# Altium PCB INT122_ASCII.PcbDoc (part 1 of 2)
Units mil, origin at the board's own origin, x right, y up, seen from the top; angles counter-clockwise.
Board outline 4500 x 3260 mil, 4 copper layers (Top Layer, GND Layer, VCC Layer, Bottom Layer), stack 61.6 mil thick; 94 components, 30 nets, 233 pads, 39 vias.
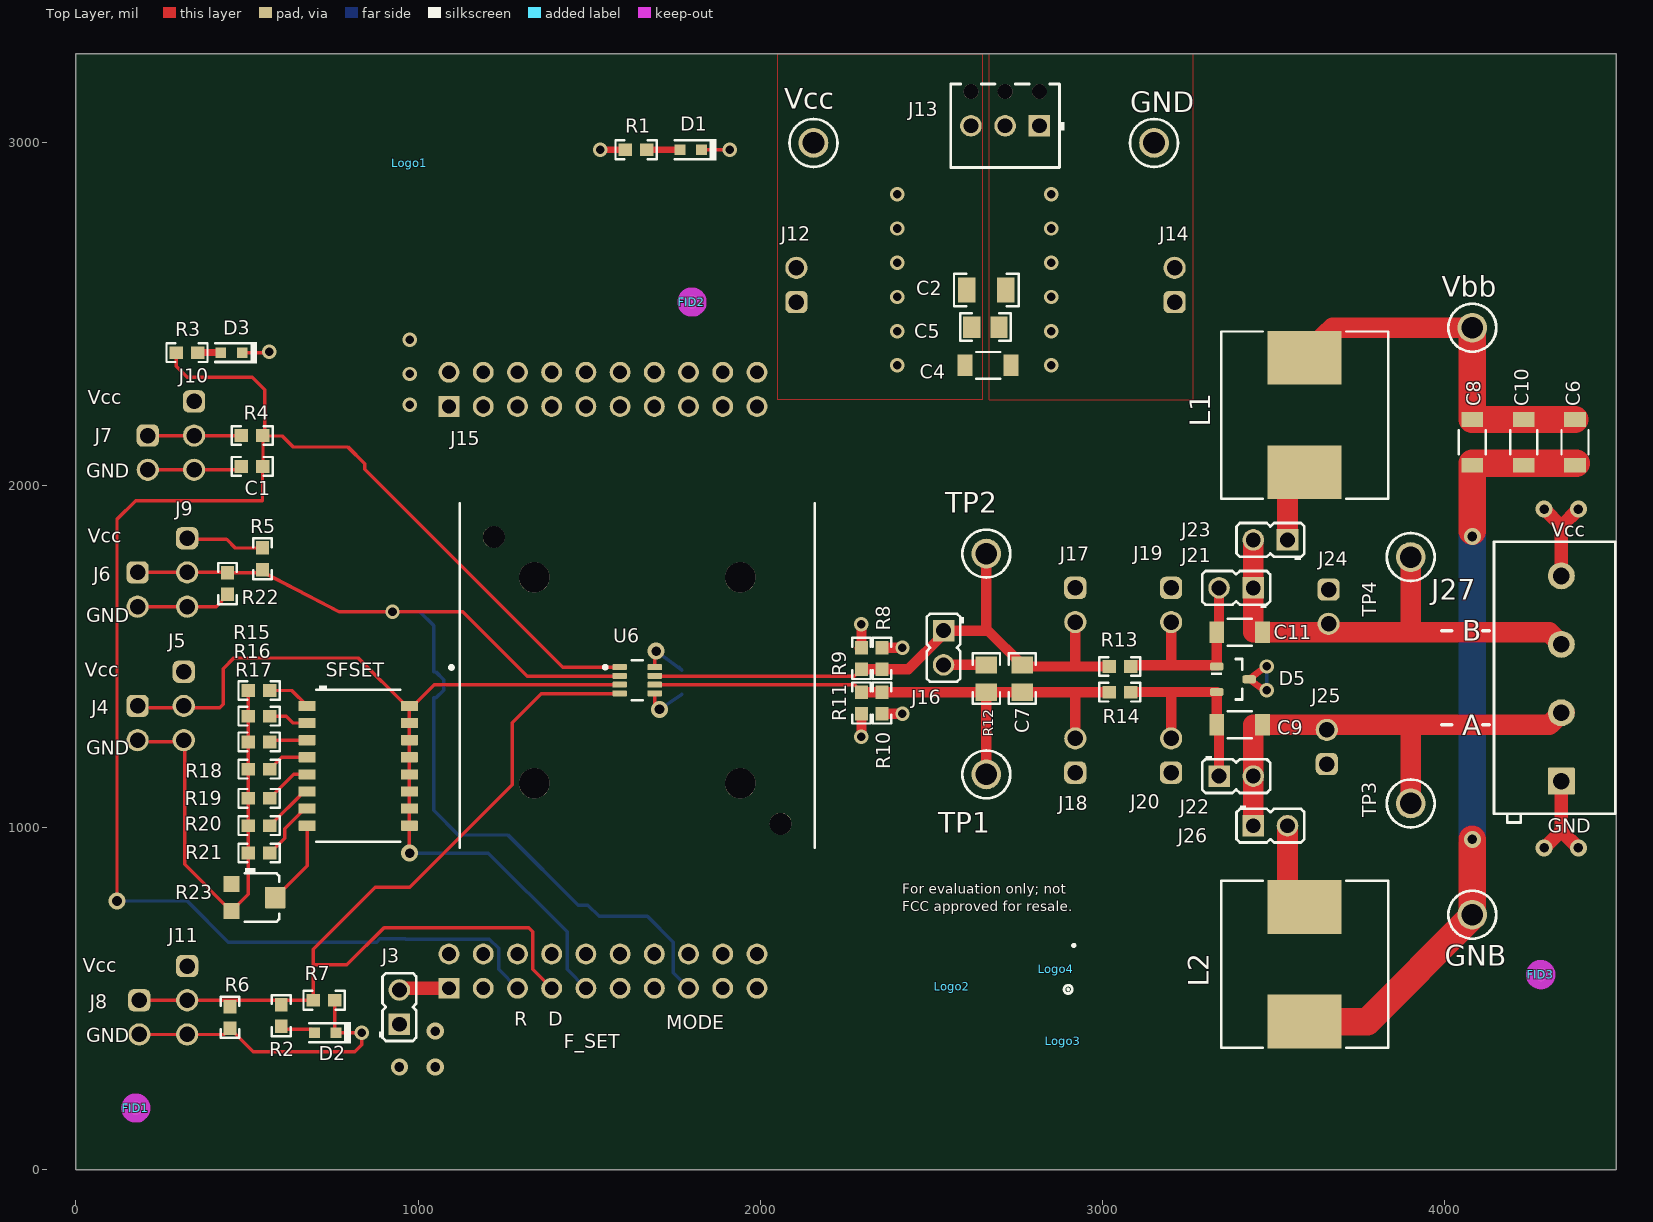
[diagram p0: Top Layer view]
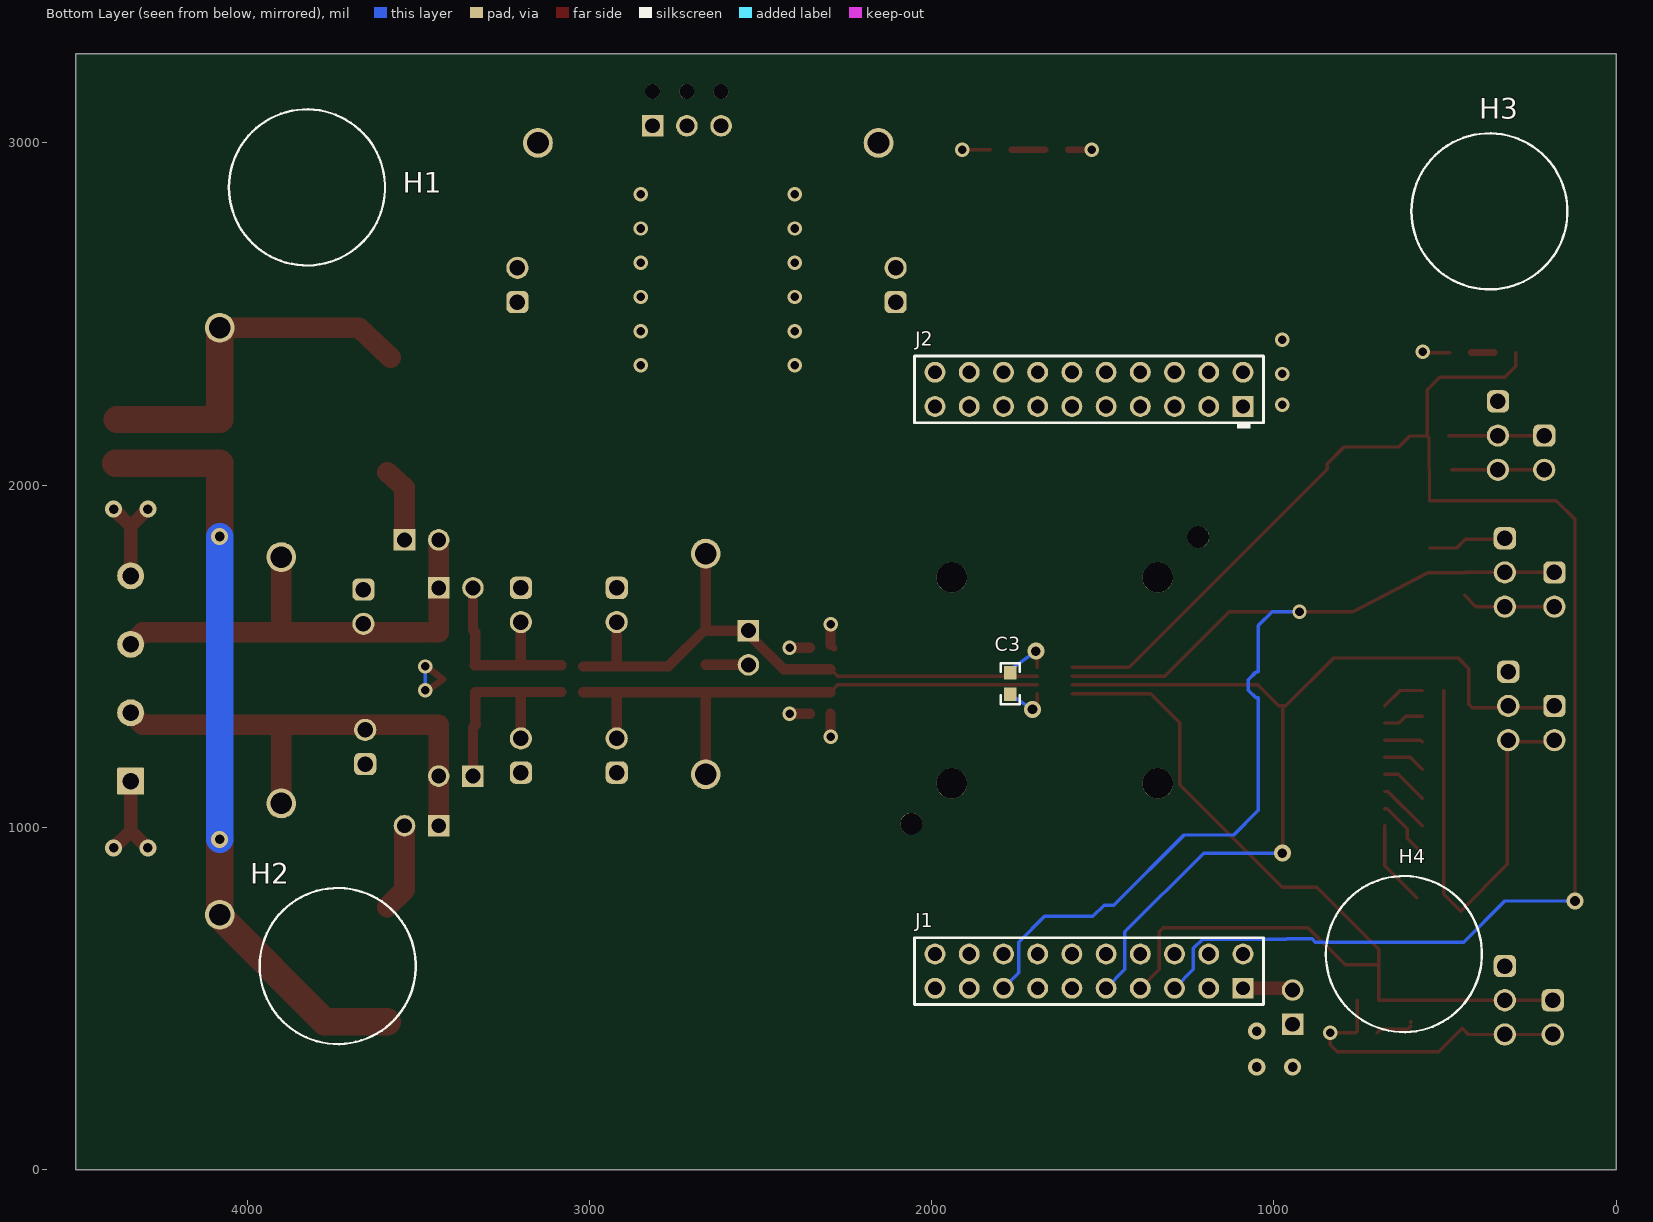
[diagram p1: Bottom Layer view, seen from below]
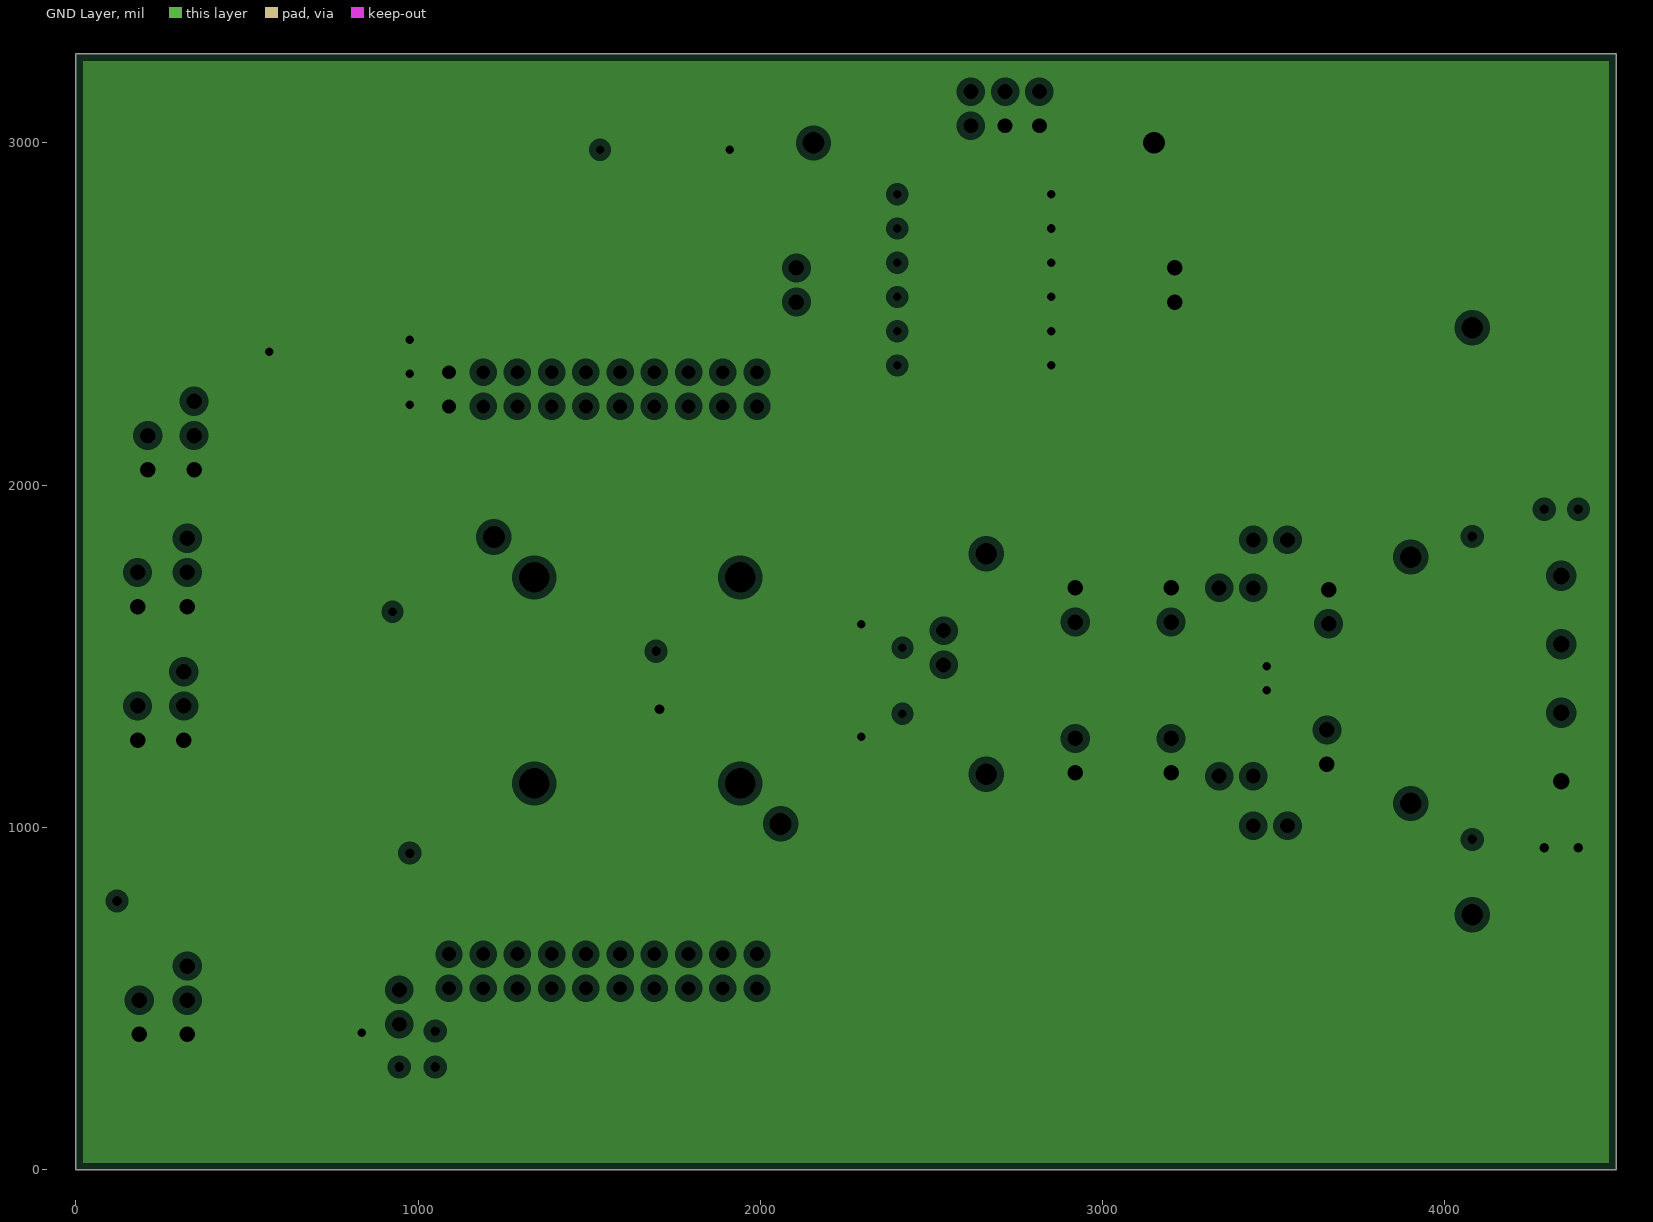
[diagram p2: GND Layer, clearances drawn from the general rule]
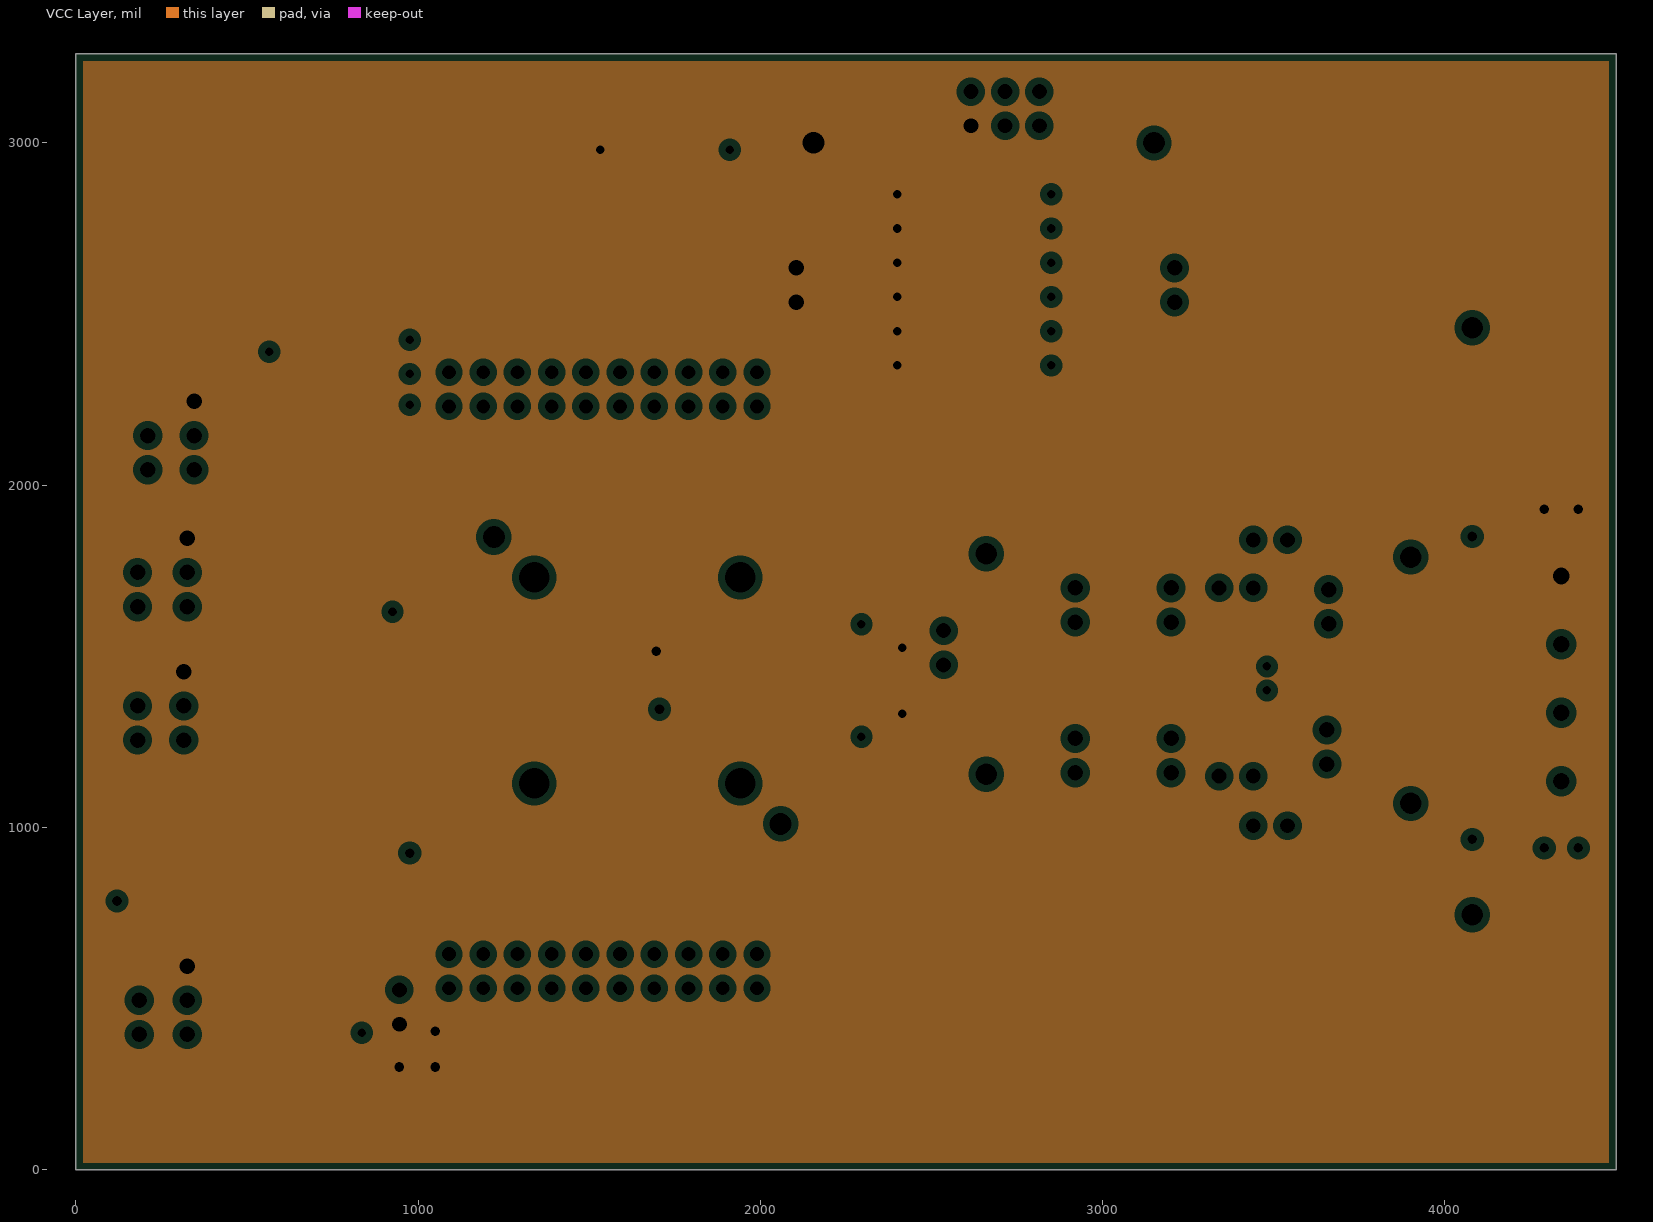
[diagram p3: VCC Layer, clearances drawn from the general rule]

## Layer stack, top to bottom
Top Solder: solder mask 0.4, Solder Resist, Dk 3.5
Top Layer: signal copper 1.4
Dielectric 1: prepreg 8, FR-4, Dk 4.2
GND Layer: plane copper 1.4, net GND_BRD
Dielectric 2: core 40, FR-4, Dk 4.2
VCC Layer: plane copper 1.4, net VCC_BRD
Dielectric 3: prepreg 8, FR-4, Dk 4.2
Bottom Layer: signal copper 1.4
Bottom Solder: solder mask 0.4, Solder Resist, Dk 3.5

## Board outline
0,0 4500,0 4500,3260 0,3260

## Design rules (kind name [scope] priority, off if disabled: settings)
AcuteAngle [All] p0: scope1count=1 scope1_0_kind=Board scope1_0_value=Board scope2count=1 scope2_0_kind=Board scope2_0_value=Board commentlength=0 minimum=4.50000000000000E+0001
AcuteAngle [All] p1: minimum=4.50000000000000E+0001 checktracksonly=FALSE
AssemblyTestPointUsage [All] p0: scope1count=1 scope1_0_kind=Board scope1_0_value=Board scope2count=1 scope2_0_kind=Board scope2_0_value=Board commentlength=0
AssemblyTestPointUsage [All] p1: valid=2
AssemblyTestpoint [All] p0: scope1count=1 scope1_0_kind=Board scope1_0_value=Board scope2count=1 scope2_0_kind=Board scope2_0_value=Board commentlength=0
BoardOutlineClearance [All] p0 off: scope1count=1 scope1_0_kind=Board scope1_0_value=Board scope2count=1 scope2_0_kind=Board scope2_0_value=Board commentlength=172 gap=75 // Protel DXP Scope 1 Expression Was: OnCopper and Not InComponentClass('Logo') and not InComponentClass('FiducialMark') and not InRegion(1000,500,4000,800) and not InPoly
BoardOutlineClearance BoardOutlineClearance_Poly [All] p0 off: scope1count=1 scope1_0_kind=Board scope1_0_value=Board scope2count=1 scope2_0_kind=Board scope2_0_value=Board commentlength=58 gap=25 // Protel DXP Scope 1 Expression Was: OnCopper and IsPoly
BoardOutlineClearance BoardOutlineClearance_MountingHoles [All] p0 off: scope1count=1 scope1_0_kind=Board scope1_0_value=Board scope2count=1 scope2_0_kind=Board scope2_0_value=Board commentlength=86 gap=40 // Protel DXP Scope 1 Expression Was: OnCopper and InComponentClass('Mounting Holes')
BoardOutlineClearance BoardOutlineClearance_MountingHoles [OnCopper and InComponentClass('Mounting Holes')] p1: gap=40 ignorepadtopadclearanceinfootprint=FALSE
BoardOutlineClearance BoardOutlineClearance_Poly [OnCopper and IsPoly] p2: gap=25 ignorepadtopadclearanceinfootprint=FALSE
BoardOutlineClearance [OnCopper and Not InComponentClass('Logo') and not InComponentClass('FiducialMark') and not InRegion(1000,500,4000,800) and not InPoly] p3: gap=75 ignorepadtopadclearanceinfootprint=FALSE
Clearance [All] p0: scope1count=1 scope1_0_kind=Board scope1_0_value=Board scope2count=1 scope2_0_kind=Board scope2_0_value=Board commentlength=0 gap=7.87
Clearance Clearance_FiducialMark [All] p0 off: scope1count=1 scope1_0_kind=Board scope1_0_value=Board scope2count=1 scope2_0_kind=Board scope2_0_value=Board commentlength=81 gap=0 // Protel DXP Scope 2 Expression Was: IsPad and InComponentClass('FiducialMark')
Clearance Clearance_Poly [All] p0 off: scope1count=1 scope1_0_kind=Board scope1_0_value=Board scope2count=1 scope2_0_kind=Board scope2_0_value=Board commentlength=48 gap=25 // Protel DXP Scope 1 Expression Was: InPolygon
Clearance Clearance_Keepouts [All] p0 off: scope1count=1 scope1_0_kind=Board scope1_0_value=Board scope2count=1 scope2_0_kind=Board scope2_0_value=Board commentlength=99 gap=0 // Protel DXP Scope 2 Expression Was: ((IsTrack Or IsArc) And Not InPoly) And IsFree and IsKeepOut
Clearance Clearance_Keepouts [((IsTrack Or IsArc) And Not InPoly) And IsFree and IsKeepOut vs ((IsTrack Or IsArc) And Not InPoly) And IsFree and IsKeepOut] p1: gap=0 ignorepadtopadclearanceinfootprint=FALSE
Clearance Clearance_Poly [InPolygon] p2: gap=25 ignorepadtopadclearanceinfootprint=FALSE except(0: Arc-Hole Track-Hole SMDPad-Hole THPad-Hole Via-Hole Fill-Hole Poly-Hole Region-Hole Text-Hole)
Clearance Clearance_FiducialMark [IsKeepOut and InComponentClass('FiducialMark') vs IsPad and InComponentClass('FiducialMark')] p3: gap=0 ignorepadtopadclearanceinfootprint=FALSE
Clearance [All] p4: gap=7.87 ignorepadtopadclearanceinfootprint=FALSE except(0: Arc-Hole Track-Hole SMDPad-Hole THPad-Hole Via-Hole Fill-Hole Poly-Hole Region-Hole Text-Hole)
ComponentClearance ComponentClearance_THtoSMT_Socket [All] p0: scope1count=1 scope1_0_kind=Component scope1_0_value=JS scope2count=1 scope2_0_kind=Component scope2_0_value=U6 commentlength=0 gap=0 collisioncheckmode=3
ComponentClearance [All] p0: scope1count=1 scope1_0_kind=Board scope1_0_value=Board scope2count=1 scope2_0_kind=Board scope2_0_value=Board commentlength=0 gap=30 collisioncheckmode=3
ComponentClearance ComponentClearance_THtoTH [All] p0 off: scope1count=1 scope1_0_kind=Board scope1_0_value=Board scope2count=1 scope2_0_kind=Board scope2_0_value=Board commentlength=54 gap=30 collisioncheckmode=3 // Protel DXP Scope 2 Expression Was: IsThruComponent
ComponentClearance ComponentClearance_THtoSMT [All] p0 off: scope1count=1 scope1_0_kind=Board scope1_0_value=Board scope2count=1 scope2_0_kind=Board scope2_0_value=Board commentlength=53 gap=40 collisioncheckmode=3 // Protel DXP Scope 2 Expression Was: IsSMTComponent
ComponentClearance ComponentClearance_SmallPassives [All] p0 off: scope1count=1 scope1_0_kind=Board scope1_0_value=Board scope2count=1 scope2_0_kind=Board scope2_0_value=Board commentlength=508 gap=14.96 collisioncheckmode=3 // Protel DXP Scope 2 Expression Was: HasFootprint('0201*') or HasFootprint('0402*') or HasFootprint('0508') or HasFootprint('0603*') or HasFootprint('0612') or HasFootprint('0805*') or HasFootprint('0815*') or HasFootprint('0830*') or HasFootprint('1206*') or HasFootprint('1210*') or HasFootprint('1808*') or HasFootprint('1812*') or HasFootprint('1825*') or HasFootprint('2010*') or HasFootprint('2220*') or HasFootprint('2225*') or HasFootprint('2512*') or HasFootprint('2728*') or HasFootprint('3518*')
ComponentClearance ComponentClearance_MountingHoles [All] p0: scope1count=1 scope1_0_kind=ComponentClass scope1_0_value="Mounting Holes" scope2count=1 scope2_0_kind=Board scope2_0_value=Board commentlength=0 gap=250 collisioncheckmode=3
ComponentClearance ComponentClearance_ScrewToNut [All] p0 off: scope1count=1 scope1_0_kind=Board scope1_0_value=Board scope2count=1 scope2_0_kind=Board scope2_0_value=Board commentlength=71 gap=5 collisioncheckmode=3 // Protel DXP Scope 2 Expression Was: (HasFootprint('Keystone_1902C'))
ComponentClearance ComponentClearance_Logo [All] p0: scope1count=1 scope1_0_kind=ComponentClass scope1_0_value=Logo scope2count=1 scope2_0_kind=Board scope2_0_value=Board commentlength=0 gap=30 collisioncheckmode=3
ComponentClearance ComponentClearance_Shunt [All] p0: scope1count=1 scope1_0_kind=ComponentClass scope1_0_value=Header scope2count=1 scope2_0_kind=ComponentClass scope2_0_value=Shunt commentlength=0 gap=0 collisioncheckmode=3
ComponentClearance ComponentClearance_MountingHoles_FiducialMarks [All] p0: scope1count=1 scope1_0_kind=ComponentClass scope1_0_value="Mounting Holes" scope2count=1 scope2_0_kind=ComponentClass scope2_0_value=FiducialMark commentlength=0 gap=50 collisioncheckmode=3
ComponentClearance ComponentClearance_L1_Multipad [All] p0: scope1count=1 scope1_0_kind=Component scope1_0_value=L1 scope2count=1 scope2_0_kind=Component scope2_0_value=L1B commentlength=0 gap=-1 collisioncheckmode=3
ComponentClearance ComponentClearance_L2_Multipad [All] p0: scope1count=1 scope1_0_kind=Component scope1_0_value=L2 scope2count=1 scope2_0_kind=Component scope2_0_value=L2B commentlength=0 gap=-1 collisioncheckmode=3
ComponentClearance ComponentClearance_C13_Multipad [All] p0: scope1count=1 scope1_0_kind=Component scope1_0_value=C13 scope2count=1 scope2_0_kind=Component scope2_0_value=C13B commentlength=0 gap=-1 collisioncheckmode=3
ComponentClearance ComponentClearance_C14_Multipad [All] p0: scope1count=1 scope1_0_kind=Component scope1_0_value=C14 scope2count=1 scope2_0_kind=Component scope2_0_value=C14B commentlength=0 gap=-1 collisioncheckmode=3
ComponentClearance ComponentClearance_THtoSMT_Socket [InComponent('JS') vs InComponent('U6')] p1: gap=0 collisioncheckmode=3 verticalgap=0 showdistances=FALSE
ComponentClearance ComponentClearance_L1_Multipad [InComponent('L1') vs InComponent('L1B')] p2: gap=-1 collisioncheckmode=3 verticalgap=100000 showdistances=FALSE
ComponentClearance ComponentClearance_L2_Multipad [InComponent('L2') vs InComponent('L2B')] p3: gap=-1 collisioncheckmode=3 verticalgap=100000 showdistances=FALSE
ComponentClearance ComponentClearance_C13_Multipad [InComponent('C13') vs InComponent('C13B')] p4: gap=-1 collisioncheckmode=3 verticalgap=100000 showdistances=FALSE
ComponentClearance ComponentClearance_C14_Multipad [InComponent('C14') vs InComponent('C14B')] p5: gap=-1 collisioncheckmode=3 verticalgap=100000 showdistances=FALSE
ComponentClearance ComponentClearance_MountingHoles_FiducialMarks [InComponentClass('Mounting Holes') vs InComponentClass('FiducialMark')] p6: gap=50 collisioncheckmode=3 verticalgap=10 showdistances=FALSE
ComponentClearance ComponentClearance_Shunt [InComponentClass('Header') vs InComponentClass('Shunt')] p7: gap=0 collisioncheckmode=3 verticalgap=0 showdistances=FALSE
ComponentClearance ComponentClearance_Logo [InComponentClass('Logo')] p8: gap=30 collisioncheckmode=3 verticalgap=10 showdistances=FALSE
ComponentClearance ComponentClearance_ScrewToNut [(HasFootprint('NY PMS 440 0025 PH')) vs (HasFootprint('Keystone_1902C'))] p9: gap=5 collisioncheckmode=3 verticalgap=10 showdistances=FALSE
ComponentClearance ComponentClearance_MountingHoles [InComponentClass('Mounting Holes')] p10: gap=250 collisioncheckmode=3 verticalgap=100000 showdistances=FALSE
ComponentClearance ComponentClearance_SmallPassives [HasFootprint('0201*') or HasFootprint('0402*') or HasFootprint('0508') or HasFootprint('0603*') or HasFootprint('0612') or HasFootprint('0805*') or HasFootprint('0815*') or HasFootprint('0830*') or HasFootprint('1206*') or HasFootprint('1210*') or HasFootprint('1808*') or HasFootprint('1812*') or HasFootprint('1825*') or HasFootprint('2010*') or HasFootprint('2220*') or HasFootprint('2225*') or HasFootprint('2512*') or HasFootprint('2728*') or HasFootprint('3518*') vs HasFootprint('0201*') or HasFootprint('0402*') or HasFootprint('0508') or HasFootprint('0603*') or HasFootprint('0612') or HasFootprint('0805*') or HasFootprint('0815*') or HasFootprint('0830*') or HasFootprint('1206*') or HasFootprint('1210*') or HasFootprint('1808*') or HasFootprint('1812*') or HasFootprint('1825*') or HasFootprint('2010*') or HasFootprint('2220*') or HasFootprint('2225*') or HasFootprint('2512*') or HasFootprint('2728*') or HasFootprint('3518*')] p11: gap=14.96 collisioncheckmode=3 verticalgap=10 showdistances=FALSE
ComponentClearance ComponentClearance_THtoSMT [IsThruComponent vs IsSMTComponent] p12: gap=40 collisioncheckmode=3 verticalgap=30 showdistances=FALSE
ComponentClearance ComponentClearance_THtoTH [IsThruComponent vs IsThruComponent] p13: gap=30 collisioncheckmode=3 verticalgap=30 showdistances=FALSE
ComponentClearance [All] p14: gap=30 collisioncheckmode=3 verticalgap=10 showdistances=FALSE
DiffPairsRouting [All] p0: scope1count=1 scope1_0_kind=Board scope1_0_value=Board scope2count=1 scope2_0_kind=Board scope2_0_value=Board commentlength=0
DiffPairsRouting [All] p1: maxlimit=100 minlimit=10 mostfreqgap=10 toplayer_minwidth=15 toplayer_maxwidth=15 toplayer_prefwidth=15 bottomlayer_minwidth=15 bottomlayer_maxwidth=15 bottomlayer_prefwidth=15 maxuncoupledlength=1000
FabricationTestPointUsage TestPointUsage [All] p0: scope1count=1 scope1_0_kind=Board scope1_0_value=Board scope2count=1 scope2_0_kind=Board scope2_0_value=Board commentlength=0 valid=2 allowmultiple=FALSE
FabricationTestPointUsage TestPointUsage [All] p1: valid=2 allowmultiple=FALSE
FabricationTestpoint Testpoint [All] p0: scope1count=1 scope1_0_kind=Board scope1_0_value=Board scope2count=1 scope2_0_kind=Board scope2_0_value=Board commentlength=0 side=3 testpointundercomponent=TRUE minsize=40 maxsize=100 preferedsize=60 minholesize=0 maxholesize=40 preferedholesize=32 testpointgrid=1
FabricationTestpoint Testpoint [All] p1: side=3 testpointundercomponent=TRUE minsize=40 maxsize=100 preferedsize=60 minholesize=0 maxholesize=40 preferedholesize=32 testpointgrid=1 allowsidetop=TRUE allowsidebottom=TRUE usegrid=TRUE gridtolerance=0.01
FanoutControl Fanout_Small [All] p0 off: scope1count=1 scope1_0_kind=Board scope1_0_value=Board scope2count=1 scope2_0_kind=Board scope2_0_value=Board commentlength=84 // Protel DXP Scope 1 Expression Was: (CompPinCount < 5)   Fanout_Small (Default Rule)
FanoutControl Fanout_Default [All] p0: scope1count=1 scope1_0_kind=Board scope1_0_value=Board scope2count=1 scope2_0_kind=Board scope2_0_value=Board commentlength=30 // Fanout_Default (Default Rule)
FanoutControl Fanout_SOIC [All] p0 off: scope1count=1 scope1_0_kind=Board scope1_0_value=Board scope2count=1 scope2_0_kind=Board scope2_0_value=Board commentlength=71 // Protel DXP Scope 1 Expression Was: IsSOIC   Fanout_SOIC (Default Rule)
FanoutControl Fanout_BGA [All] p0 off: scope1count=1 scope1_0_kind=Board scope1_0_value=Board scope2count=1 scope2_0_kind=Board scope2_0_value=Board commentlength=69 // Protel DXP Scope 1 Expression Was: IsBGA   Fanout_BGA (Default Rule)
FanoutControl Fanout_LCC [All] p0 off: scope1count=1 scope1_0_kind=Board scope1_0_value=Board scope2count=1 scope2_0_kind=Board scope2_0_value=Board commentlength=69 // Protel DXP Scope 1 Expression Was: IsLCC   Fanout_LCC (Default Rule)
FanoutControl Fanout_LCC [IsLCC] p1: bgadir=Out bgaviamode=Centered fanoutstyle=Auto fanoutdirection=Alternating viagrid=1 // Fanout_LCC (Default Rule)
FanoutControl Fanout_BGA [IsBGA] p2: bgadir=Out bgaviamode=Centered fanoutstyle=Auto fanoutdirection=Alternating viagrid=1 // Fanout_BGA (Default Rule)
FanoutControl Fanout_Default [All] p4: bgadir=Out bgaviamode=Centered fanoutstyle=Auto fanoutdirection=Alternating viagrid=1 // Fanout_Default (Default Rule)
FanoutControl Fanout_Small [(CompPinCount < 5)] p5: bgadir=Out bgaviamode=Centered fanoutstyle=Auto fanoutdirection=OutThenIn viagrid=1 // Fanout_Small (Default Rule)
Height [All] p0: scope1count=1 scope1_0_kind=Board scope1_0_value=Board scope2count=1 scope2_0_kind=Board scope2_0_value=Board commentlength=0
HoleSize [All] p0: scope1count=1 scope1_0_kind=Board scope1_0_value=Board scope2count=1 scope2_0_kind=Board scope2_0_value=Board commentlength=0 absolutevalues=TRUE maxlimit=251 minlimit=7.87 maxpercent=80.000 minpercent=20.000
HoleSize [All] p1: absolutevalues=TRUE maxlimit=251 minlimit=7.87 maxpercent=80.000 minpercent=20.000
HoleToHoleClearance [All] p0: scope1count=1 scope1_0_kind=Board scope1_0_value=Board scope2count=1 scope2_0_kind=Board scope2_0_value=Board commentlength=0
LayerPairs [All] p0: scope1count=1 scope1_0_kind=Board scope1_0_value=Board scope2count=1 scope2_0_kind=Board scope2_0_value=Board commentlength=0 enforce=TRUE
MinimumAnnularRing [All] p0: scope1count=1 scope1_0_kind=Board scope1_0_value=Board scope2count=1 scope2_0_kind=Board scope2_0_value=Board commentlength=0 minimumring=8
MinimumAnnularRing MinimumAnnularRing_ThermalPadVias [All] p0 off: scope1count=1 scope1_0_kind=Board scope1_0_value=Board scope2count=1 scope2_0_kind=Board scope2_0_value=Board commentlength=63 minimumring=5.91 // Protel DXP Scope 1 Expression Was: IsVia and InAnyComponent
MinimumAnnularRing MinimumAnnularRing_ThermalPadVias [IsVia and InAnyComponent] p1: minimumring=5.91
MinimumAnnularRing [All] p2: minimumring=8
MinimumSolderMaskSliver [All] p0: scope1count=1 scope1_0_kind=Board scope1_0_value=Board scope2count=1 scope2_0_kind=Board scope2_0_value=Board commentlength=0
MinimumSolderMaskSliver MinimumSolderMaskSliver_Logo [All] p0: scope1count=1 scope1_0_kind=ComponentClass scope1_0_value=Logo scope2count=1 scope2_0_kind=ComponentClass scope2_0_value=Logo commentlength=0
MinimumSolderMaskSliver MinimumSolderMaskSliver_Logo [InComponentClass('Logo') vs InComponentClass('Logo')] p1: minsoldermaskwidth=0.7
MinimumSolderMaskSliver [All] p2: minsoldermaskwidth=3.94
NetAntennae [All] p0: scope1count=1 scope1_0_kind=Board scope1_0_value=Board scope2count=1 scope2_0_kind=Board scope2_0_value=Board commentlength=0
PasteMaskExpansion [All] p0: scope1count=1 scope1_0_kind=Board scope1_0_value=Board scope2count=1 scope2_0_kind=Board scope2_0_value=Board commentlength=0 expansion=0
PlaneClearance [All] p0: scope1count=1 scope1_0_kind=Board scope1_0_value=Board scope2count=1 scope2_0_kind=Board scope2_0_value=Board commentlength=0 clearance=20
PlaneClearance [All] p1: clearance=20
PlaneConnect [All] p0: scope1count=1 scope1_0_kind=Board scope1_0_value=Board scope2count=1 scope2_0_kind=Board scope2_0_value=Board commentlength=0 planeconnectstyle=Relief reliefexpansion=10 reliefentries=4 reliefconductorwidth=10 reliefairgap=10
PlaneConnect [All] p1: planeconnectstyle=Relief reliefexpansion=10 reliefentries=4 reliefconductorwidth=10 reliefairgap=10
PolygonConnect [All] p0: scope1count=1 scope1_0_kind=Board scope1_0_value=Board scope2count=1 scope2_0_kind=Board scope2_0_value=Board commentlength=0 connectstyle=Relief reliefconductorwidth=15 reliefentries=4 polygonreliefangle="90 Angle"
PolygonConnect [All] p1: connectstyle=Relief reliefconductorwidth=15 reliefentries=4 polygonreliefangle="90 Angle" airgapwidth=7
RoutingCorners [All] p0: scope1count=1 scope1_0_kind=Board scope1_0_value=Board scope2count=1 scope2_0_kind=Board scope2_0_value=Board commentlength=0 cornerstyle=45-Degree minsetback=100 maxsetback=100
RoutingLayers [All] p0: scope1count=1 scope1_0_kind=Board scope1_0_value=Board scope2count=1 scope2_0_kind=Board scope2_0_value=Board commentlength=0 top layer=Automatic bottom layer=Automatic
RoutingPriority [All] p0: scope1count=1 scope1_0_kind=Board scope1_0_value=Board scope2count=1 scope2_0_kind=Board scope2_0_value=Board commentlength=0
RoutingTopology [All] p0: scope1count=1 scope1_0_kind=Board scope1_0_value=Board scope2count=1 scope2_0_kind=Board scope2_0_value=Board commentlength=0 topology=Shortest
RoutingVias [All] p0: scope1count=1 scope1_0_kind=Board scope1_0_value=Board scope2count=1 scope2_0_kind=Board scope2_0_value=Board commentlength=0 holewidth=25 width=42 viastyle="Through Hole" minholewidth=7.87 minwidth=26 maxholewidth=40 maxwidth=65
RoutingVias ThermalPadVias [All] p0 off: scope1count=1 scope1_0_kind=Board scope1_0_value=Board scope2count=1 scope2_0_kind=Board scope2_0_value=Board commentlength=63 holewidth=7.87 width=19.68 viastyle="Through Hole" minholewidth=7.87 minwidth=19.68 maxholewidth=12.99 maxwidth=23.62 // Protel DXP Scope 1 Expression Was: IsVia and InAnyComponent
RoutingVias ThermalPadVias [IsVia and InAnyComponent] p1: holewidth=7.87 width=19.68 viastyle="Through Hole" minholewidth=7.87 minwidth=19.68 maxholewidth=12.99 maxwidth=23.62
RoutingVias [All] p2: holewidth=25 width=42 viastyle="Through Hole" minholewidth=7.87 minwidth=26 maxholewidth=40 maxwidth=65
ShortCircuit [All] p0: scope1count=1 scope1_0_kind=Board scope1_0_value=Board scope2count=1 scope2_0_kind=Board scope2_0_value=Board commentlength=0 allowed=FALSE
SilkToBoardRegionClearance [All] p0 off: scope1count=1 scope1_0_kind=Board scope1_0_value=Board scope2count=1 scope2_0_kind=Board scope2_0_value=Board commentlength=130 // Protel DXP Scope 1 Expression Was: Not ((IsComment or IsDesignator) And (Hide <> 'False')) and not InRegion(1000,500,4000,800)
SilkToBoardRegionClearance [Not ((IsComment or IsDesignator) And (Hide <> 'False')) and not InRegion(1000,500,4000,800)] p1:
SilkToSilkClearance [All] p0: scope1count=1 scope1_0_kind=Board scope1_0_value=Board scope2count=1 scope2_0_kind=Board scope2_0_value=Board commentlength=0
SilkToSilkClearance SilkToSilkClearance_Pb-FreeLogo [All] p0 off: scope1count=1 scope1_0_kind=Board scope1_0_value=Board scope2count=1 scope2_0_kind=Board scope2_0_value=Board commentlength=120 // Protel DXP Scope 2 Expression Was: (HasFootprint('Pb-Free_Overlay_Medium') OR HasFootprint('Pb-Free_Overlay_Small'))
SilkToSilkClearance SilkToSilkClearance_Pb-FreeLogo [(HasFootprint('Pb-Free_Overlay_Medium') OR HasFootprint('Pb-Free_Overlay_Small')) vs (HasFootprint('Pb-Free_Overlay_Medium') OR HasFootprint('Pb-Free_Overlay_Small'))] p1: silktosilkclearance=0
SilkToSilkClearance [All] p2: silktosilkclearance=4
SilkToSolderMaskClearance "Silk to Solder Mask Opening" [All] p0: scope1count=1 scope1_0_kind=Board scope1_0_value=Board scope2count=1 scope2_0_kind=Board scope2_0_value=Board commentlength=0
SilkToSolderMaskClearance SilkToComponentPadClearance [All] p0 off: scope1count=1 scope1_0_kind=Board scope1_0_value=Board scope2count=1 scope2_0_kind=Board scope2_0_value=Board commentlength=87 // Protel DXP Scope 1 Expression Was: (IsPad or IsFill or IsRegion) and InAnycomponent
SilkToSolderMaskClearance SilkToComponentPadClearance [(IsPad or IsFill or IsRegion) and InAnycomponent] p1: minsilkscreentomaskgap=5 clearancetoexposedcopper=TRUE
SilkToSolderMaskClearance "Silk to Solder Mask Opening" [All] p2: minsilkscreentomaskgap=4 clearancetoexposedcopper=FALSE
SolderMaskExpansion [All] p0: scope1count=1 scope1_0_kind=Board scope1_0_value=Board scope2count=1 scope2_0_kind=Board scope2_0_value=Board commentlength=0 expansion=1.97
SolderMaskExpansion [All] p1: expansion=1.97
UnRoutedNet [All] p0: scope1count=1 scope1_0_kind=Board scope1_0_value=Board scope2count=1 scope2_0_kind=Board scope2_0_value=Board commentlength=0
UnpouredPolygon [All] p0: scope1count=1 scope1_0_kind=Board scope1_0_value=Board scope2count=1 scope2_0_kind=Board scope2_0_value=Board commentlength=0
Width [All] p0: scope1count=1 scope1_0_kind=Board scope1_0_value=Board scope2count=1 scope2_0_kind=Board scope2_0_value=Board commentlength=0 maxlimit=100 minlimit=6 preferedwidth=10
Width [All] p1: maxlimit=100 minlimit=6 preferedwidth=10 checkconnectedcopper=TRUE
14 further rules are at their usual default settings.

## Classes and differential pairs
component class Header: J3 J4 J5 J6 J7 J8 J9 J10 J11 J12 J14 J16 J17 J18 J19 J20 J21 J22 J23 J24 J25 J26 JD1 JF1 JM1 JR1 TL_A tn
component class AssemblyNote: ZZ1 ZZ2 ZZ3 ZZ4
component class FiducialMark: FID1 FID2 FID3
component class EVM_Hardware: FID1 FID2 FID3 H1 H2 H3 H4 Logo1 Logo2 Logo3 Logo4 SH-J1 SH-J2 ZZ1 ZZ2 ZZ3 ZZ4
component class Logo: Logo1

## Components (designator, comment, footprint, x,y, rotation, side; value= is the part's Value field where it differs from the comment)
C1 "06035A150JAT2A" 0603 515,2055 r180 top
C2 "12063C105KAT2A" 1206 2660,2570 r0 top
C3 "C0603C104K9PAC7867" 0603 1770,1420 r90 bottom
C4 "C3216X7R1V106K160AC" 1206_180 2665,2350 r0 top
C5 "GRM21BR61A476ME15L" 0805_HV 2657.5,2461.85 r180 top
C6 "C3216X5R1E476M160AC" 1206_190 4380,2125 r90 top
C7 "08053C104KAT2A" 0805_HV 2765,1435 r270 top
C8 "CGA5L2X7R2A105K160AA" 1206_180 4080,2125 r90 top
C9 "CGA5L2X7R2A105K160AA" 1206_180 3400.25,1300.3 r180 top
C10 "CL31B106KBHNNNE" 1206_180 4230,2125 r90 top
C11 "CGA5L2X7R2A105K160AA" 1206_180 3400.25,1570.3 r180 top
D1 "150060BS75000" WL-SMCW_Blue 1796.5,2980 r180 top
D2 "150060GS75000" WL-SMCW_GREEN 728.7,400 r180 top
D3 "150060RS75000" WL-SMCW_RED 454.45,2387.2 r180 top
D5 "CDSOT23-T12C" SOT-23 3380.56,1432.86 r0 top
FID1 "Fiducial" Fiducial10-20 175,180 r0 top
FID2 "Fiducial" Fiducial10-20 1800,2535 r0 top
FID3 "Fiducial" Fiducial10-20 4280,570 r90 top
GNB "5011" Keystone5011 4080,745 r0 top
GND "5011" Keystone5011 3150,3000 r180 top
H1 "SJ-5303 (CLEAR)" Bumpon_SJ5003Transparent 3825,2870 r90 bottom
H2 "SJ-5303 (CLEAR)" Bumpon_SJ5003Transparent 3735,595 r90 bottom
H3 "SJ-5303 (CLEAR)" Bumpon_SJ5003Transparent 370,2800 r90 bottom
H4 "SJ-5303 (CLEAR)" Bumpon_SJ5003Transparent 620,630 r180 bottom
J1 "SSQ-110-23-F-D" Samtec_SSQ-110-23-F-D 1540,580 r0 bottom
J2 "SSQ-110-23-F-D" Samtec_SSQ-110-23-F-D 1540,2280 r0 bottom
J3 "961102-6404-AR" 3M_961102-6404-AR 945,475 r90 top
J4 "61300211121" WURTH_61300211121 180,1305 r270 top
J5 "61300311121" WURTH_61300311121 315,1355 r270 top
J6 "61300211121" WURTH_61300211121 180,1695 r270 top
J7 "61300211121" WURTH_61300211121 210,2095 r270 top
J8 "61300211121" WURTH_61300211121 185,445 r270 top
J9 "61300311121" WURTH_61300311121 325,1745 r270 top
J10 "61300311121" WURTH_61300311121 345,2145 r270 top
J11 "61300311121" WURTH_61300311121 325,495 r270 top
J12 "61300211121" WURTH_61300211121 2105,2585 r90 top
J13 "1725669" Phoenix_1725669 2715,3050 r180 top
J14 "61300211121" WURTH_61300211121 3210,2585 r90 top
J15 "SK02-0008SOP-GS-04A" FP-SK02-0008SOP-GS-04A_SOCKET-MFG 1640,1415 r0 top
J16 "961102-6404-AR" 3M_961102-6404-AR 2535,1525 r270 top
J17 "61300211121" WURTH_61300211121 2920,1650 r270 top
J18 "61300211121" WURTH_61300211121 2920,1210 r90 top
J19 "61300211121" WURTH_61300211121 3200,1650 r270 top
J20 "61300211121" WURTH_61300211121 3200,1210 r90 top
J21 "961102-6404-AR" 3M_961102-6404-AR 3390,1700 r180 top
J22 "961102-6404-AR" 3M_961102-6404-AR 3390,1150 r0 top
J23 "961102-6404-AR" 3M_961102-6404-AR 3490,1840 r180 top
J24 "61300211121" WURTH_61300211121 3660,1645 r270 top
J25 "61300211121" WURTH_61300211121 3655,1235 r90 top
J26 "961102-6404-AR" 3M_961102-6404-AR 3490,1005 r0 top
J27 "ED120/4DS" On-Shore_ED120_4DS 4340,1435 r90 top
L1 "MSS1278T-124KLB" MSS1278T 3590,2205 r270 top
L2 "MSS1278T-124KLB" MSS1278T 3590,600 r270 top
Logo1 "Texas Instruments" TI_Stacked_Overlay_Small 975,2940 r0 top
Logo2 "CE Mark" CE_Mark_5mm 2560,535 r0 top
Logo3 "FCC disclaimer" FCC_disclaimer 2885,375 r270 top
Logo4 "WEEE logo" WEEE_Minimum 2865,585 r0 top
R1 "CRCW06031K00JNEA" 0603 1636.5,2980 r0 top
R2 "CRCW06031K00JNEA" 0603 599.8,450 r270 top
R3 "CRCW06031K00JNEA" 0603 324.45,2387.2 r0 top
R4 "RCS06030000Z0EA" 0603 515,2145 r0 top
R5 "RC1608J103CS" 0603 545,1785 r90 top
R6 "RCP0603W50R0GEB" 0603 450,445 r90 top
R7 "RC1608J103CS" 0603 725,495 r180 top
R8 "RC0603JR-0715KL" 0603 2355,1493.7 r90 top
R9 "RC0603FR-0712K4L" 0603 2295,1493.7 r270 top
R10 "RC0603FR-0712K4L" 0603 2355,1363.5 r270 top
R11 "RC0603JR-0715KL" 0603 2295,1363.5 r90 top
R12 "ERJ-P06J121V" 0805_HV 2660,1435 r90 top
R13 "RCS06030000Z0EA" 0603 3050,1470.26 r0 top
R14 "RCS06030000Z0EA" 0603 3050,1395 r0 top
R15 "ERJ-3EKF1501V" 0603 535,1400 r0 top
R16 "CRCW06034K42FKEA" 0603 535,1325 r0 top
R17 "CRCW06039K31FKEA" 0603 535,1250 r0 top
R18 "RC0603FR-0712K4L" 0603 535,1170 r0 top
R19 "RC0603FR-0719K1L" 0603 535,1085 r0 top
R20 "RC0603FR-0749K9L" 0603 535,1005 r0 top
R21 "CRCW060376K8FKEA" 0603 535,925 r0 top
R22 "RCP0603W50R0GEB" 0603 442.5,1712.5 r90 top
R23 "TC33X-2-103E" Bourns_TC33X-2 525,795 r0 top
SFSET "1-1571983-1" SW_1-1571983-1 825,1180 r0 top
SH-J1 "M7582-05" Harwin_M7582-05 4898,161 r90 top
SH-J2 "M7582-05" Harwin_M7582-05 4648,161 r90 top
TP1 "5012" Keystone5012 2660,1155 r0 top
TP2 "5012" Keystone5012 2660,1800 r0 top
TP3 "5012" Keystone5012 3900,1070 r0 top
TP4 "5012" Keystone5012 3900,1790 r0 top
U6 "THVD8000DDF" DDF0008A-MFG 1640,1430 r0 top
Vbb "5010" Keystone5010 4080,2460 r0 top
Vcc "5010" Keystone5010 2155,3000 r180 top
ZZ1 "This Assembly Note is for PCB labels only" AssemblyNoteLabel 185,3938 r0 top
ZZ2 "These assemblies are ESD sensitive, ESD precautions shall be observed." AssemblyNote 185,3829.11 r0 top
ZZ3 "These assemblies must be clean and free from flux and all contaminants. Use of no clean flux is not acceptable." AssemblyNote 185,3740.56 r0 top
ZZ4 "These assemblies must comply with workmanship standards IPC-A-610 Class 2, unless otherwise specified." AssemblyNote 185,3652 r0 top

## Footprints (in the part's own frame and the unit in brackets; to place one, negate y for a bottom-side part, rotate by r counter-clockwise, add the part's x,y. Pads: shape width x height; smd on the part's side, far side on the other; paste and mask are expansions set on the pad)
3M_961102-6404-AR [mm] "Header, 2.54mm, 2x1, TH"
  rect 1.6x1.6 hole 1.1: 1(-1.27,0)
  round 1.6 hole 1.1: 2(1.27,0)
  silkscreen extent -2.52,-1.25 2.52,1.5
0603 [mm] "0603 from SM-752 data"
  rect 1x0.95 smd: 1(-0.8,0) 2(0.8,0)
  silkscreen extent -1.52,-0.69 1.52,0.69
0805_HV [mil] "0805 with 30mil clearance between pads"
  rect 50x63 smd: 1(-40,0) 2(40,0)
  silkscreen extent -74,-40 74,40
1206 [mm] "1206 from SM-752 data"
  rect 1.3x1.85 smd: 1(-1.45,0) 2(1.45,0)
  silkscreen extent -2.4,-1.21 2.4,1.21
1206_180 [mm] "1206_180"
  rect 1.1x1.6 smd: 1(-1.7,0) 2(1.7,0)
  silkscreen extent -0.9,-1 0.9,1
1206_190 [mm] "1206_190"
  rect 1.1x1.6 smd: 1(-1.7,0) 2(1.7,0)
  silkscreen extent -0.9,-1 0.9,1
AssemblyNote [mil] "Assembly Note"
AssemblyNoteLabel [mil] "Assembly Note for PCB Labels"
Bourns_TC33X-2 [mm] "SMD, 3-Leads, Body 3.8x3.6mm"
  rrect8% 1.2x1.2 smd: 1(-1.8,1) 3(-1.8,-1)
  rrect7% 1.5x1.6 smd: 2(1.45,0)
  silkscreen extent -0.8,-1.8 1.75,2.2
Bumpon_SJ5003Transparent [mil] "3M Hemispherical Bumpon transparent"
  round 1 on Mech4: 0(0,0)
  silkscreen extent -228,-228 228,228
CE_Mark_5mm [mil] "Minimum text height for CE Mark"
DDF0008A-MFG [mm]
  rrect22% 1.05x0.45 smd paste+0 mask+0: 1(-1.3,0.975) 2(-1.3,0.325) 3(-1.3,-0.325) 4(-1.3,-0.975) 5(1.3,-0.975) 6(1.3,-0.325) 7(1.3,0.325) 8(1.3,0.975)
  silkscreen extent -2.5,-1.48 0.4,1.48
FCC_disclaimer [mil]
Fiducial10-20 [mm]
  round 1 smd mask+0: 1(0,0)
  Top Layer keep-out circle w1.178: c0,0 r0.5
FP-SK02-0008SOP-GS-04A_SOCKET-MFG [mil]
  rrect29% 41x14 smd paste-39370.1 mask+0: 1(-51,52.5) 2(-51,26.9) 3(-51,1.3) 4(-51,-24.3) 5(51,-24.3) 6(51,1.3) 7(51,26.9) 8(51,52.5)
  round 64 hole 64 unplated paste-39370.1 mask+0: ""(-419,433.5) ""(419,-404.5)
  round 89 hole 89 unplated paste-39370.1 mask+0: ""(-301,-286.5) ""(-301,315.5) ""(301,-286.5) ""(301,315.5)
  silkscreen extent -548,-474 519,532
Harwin_M7582-05 [mil] "Single Operation 2.54mm Pitch Open Top Jumper Socket"
Keystone5010 [mil] "Keystone Multipurpose loops"
  round 87 hole 63: 1(0,0)
  silkscreen extent -70,-70 70,70
Keystone5011 [mil] "Keystone Multipurpose loops"
  round 87 hole 63: 1(0,0)
  silkscreen extent -70,-70 70,70
Keystone5012 [mil] "Keystone Multipurpose loops"
  round 87 hole 63: 1(0,0)
  silkscreen extent -70,-70 70,70
MSS1278T [mm] "Coilcraft recommended land pattern.  Document 598-2 rev 10/20/08"
  rect 4x5.5 smd: 1(-4.25,0) 2(4.25,0)
  silkscreen extent -6.2,-6.2 6.2,6.2
On-Shore_ED120_4DS [mm] "ONSHORE"
  rrect5% 2x2 hole 1.25: 1(-7.62,0)
  round 2 hole 1.25: 2(-2.54,0) 3(2.54,0) 4(7.62,0)
  silkscreen extent -10.68,-4 10.16,5
Phoenix_1725669 [mm] "Terminal Block, 3x1, 2.54 mm, TH"
  rect 1.6x1.6 hole 1.1: 1(-2.54,0)
  round 1.6 hole 1.1: 2(0,0) 3(2.54,0)
  round 1.1 hole 1.1 unplated mask+0: 4(-2.54,-2.54) 5(0,-2.54) 6(2.54,-2.54)
  silkscreen extent -4.4,-3.1 4.04,3.1
Samtec_SSQ-110-23-F-D [mm] "Receptacle, 2.54mm, 10x2, TH"
  rect 1.55x1.55 hole 1.02: 1(-11.43,1.27)
  round 1.55 hole 1.02: 2(-11.43,-1.27) 3(-8.89,1.27) 4(-8.89,-1.27) 5(-6.35,1.27) 6(-6.35,-1.27) 7(-3.81,1.27) 8(-3.81,-1.27) 9(-1.27,1.27) 10(-1.27,-1.27) 11(1.27,1.27) 12(1.27,-1.27) 13(3.81,1.27) 14(3.81,-1.27) 15(6.35,1.27) 16(6.35,-1.27) 17(8.89,1.27) 18(8.89,-1.27) 19(11.43,1.27) 20(11.43,-1.27)
  silkscreen extent -12.95,-2.48 12.95,2.48
SOT-23 [mm] "SOT23, 3-Leads, Body 2.9x1.3mm, Pitch 0.95mm, Lead Span 2.5mm, IPC Medium Density"
  rrect50% 1x0.6 smd: 1(-1.2,0.95) 2(-1.2,-0.95) 3(1.2,0)
  silkscreen extent -1.63,-1.5 0.7,1.5
SW_1-1571983-1 [mm] "SMD, 16-Leads, Body 11.28x6.2mm"
  rrect13% 1.27x0.76 smd: 1(-3.795,4.445) 2(-3.795,3.175) 3(-3.795,1.905) 4(-3.795,0.635) 5(-3.795,-0.635) 6(-3.795,-1.905) 7(-3.795,-3.175) 8(-3.795,-4.445) 9(3.795,-4.445) 10(3.795,-3.175) 11(3.795,-1.905) 12(3.795,-0.635) 13(3.795,0.635) 14(3.795,1.905) 15(3.795,3.175) 16(3.795,4.445)
  silkscreen extent -3.1,-5.64 3.1,5.95
TI_Stacked_Overlay_Small [mil]
WEEE_Minimum [mil] "WEEElie bin"
  silkscreen extent 22,-71 54,74
WL-SMCW_Blue [mm] "SMD, 2-Leads, Body 1.6x0.8mm"
  rect 0.8x0.8 smd: 1(-0.8,0) 2(0.8,0)
  silkscreen extent -1.9,-0.8 1.2,0.8
WL-SMCW_GREEN [mm] "WURTH"
  rect 0.8x0.8 smd: 1(-0.8,0) 2(0.8,0)
  silkscreen extent -1.9,-0.8 1.2,0.8
WL-SMCW_RED [mm] "WURTH"
  rect 0.8x0.8 smd: 1(-0.8,0) 2(0.8,0)
  silkscreen extent -1.9,-0.8 1.2,0.8
WURTH_61300211121 [mm] "Header, 2.54mm, 2x1, TH"
  rrect50% 1.65x1.65 hole 1.15: 1(-1.27,0)
  round 1.65 hole 1.15: 2(1.27,0)
WURTH_61300311121 [mm] "Header, 2.54mm, 3x1, TH"
  rrect50% 1.65x1.65 hole 1.15: 1(-2.54,0)
  round 1.65 hole 1.15: 2(0,0) 3(2.54,0)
